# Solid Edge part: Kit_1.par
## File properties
Sűrűség: 0,000 kg/m^3
Pontosság: 0,990
Author: ahadarics
Last saved by: ahadarics
Revision: 76
Username: ahadarics
Dokumentum tartalom típus: 0
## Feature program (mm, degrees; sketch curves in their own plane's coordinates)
base feature "unnamed BaseFeature 1"
sketch for "Furat_1" plane through (-47.6845, 0, -79.5) normal (-0.999962, 0, -0.008727) x-axis (0, -1, 0)
hole "Furat_1" diameter 8.566 finite
sketch for "Furat_2" plane through (0, 0, -87) normal (0, 0, -1) x-axis (0, -1, 0)
  hole centre (-36, 36) bore radius 4.188
hole "Furat_2" nominal diameter 10 through
sketch for "unnamed Hole 1" plane through (0, 0, -87) normal (0, 0, -1) x-axis (0, -1, 0)
  hole centre (36, 36) bore radius 4.188
hole "unnamed Hole 1" through
sketch for "unnamed Hole 2" plane through (0, 0, -87) normal (0, 0, -1) x-axis (0, -1, 0)
  hole centre (36, -36) bore radius 4.188
hole "unnamed Hole 2" through
sketch for "unnamed Hole 3" plane through (0, 0, -87) normal (0, 0, -1) x-axis (0, -1, 0)
  hole centre (-36, -36) bore radius 4.188
hole "unnamed Hole 3" through
pattern "unnamed Pattern 1" of "Furat_2", "unnamed Hole 1", "unnamed Hole 2", "unnamed Hole 3"
thread "unnamed Thread 1"
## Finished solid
Body 1: solid body, 307 faces, 742 edges, 452 vertices.
  Faces by surface: plane 139, cylinder 73, swept 60, cone 24, torus 10, spline 1
  Edges by curve: line 421, circle 152, spline 120, ellipse 32, curve on surface 17
Bounding box of the edges (mm; curved faces can reach further): 95.500 x 95.500 x 15.000, from (-47.75, -47.75, -87) to (47.75, 47.75, -72).
Cylindrical faces by radius (mm): R0.2 x48, R0.2017 x2, R0.2018 x2, R4.188 x4, R4.283 x1, R4.9 x4, R5.15 x4, R6.75 x4, R10.3 x1, R10.95 x1, R11.5 x1, R12.5 x1
Conical faces (half-angle, radius in mm at the cone's reference point): 0.5 deg R10 x4, 0.5 deg R13.5 x2, 7 deg R11.7695 x1, 14 deg R10.15 x1, 14 deg R10.557 x1, 17 deg R10.15 x1, 23 deg R10.9211 x1, 42.5 deg R10.137 x1, 45 deg R4.185 x4, 45 deg R4.985 x4, 45 deg R11.1 x1, 84 deg R10.512 x1, 85 deg R12.1625 x1, 87 deg R10.2157 x1
Toroidal faces (ring radius, tube radius in mm): R4.7 r0.2 x8, R10.9008 r0.225 x1, R11.3914 r0.325 x1
Planar faces by outward normal: +x 14, +y 14, +z 1, -x 16, -y 13, -z 19, oblique 62
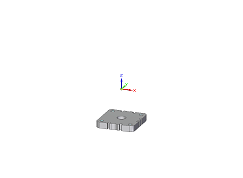
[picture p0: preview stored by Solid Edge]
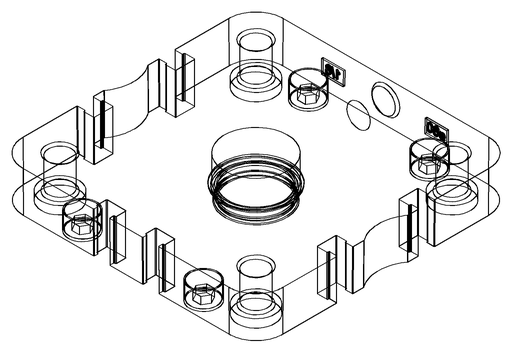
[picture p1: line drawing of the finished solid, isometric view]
